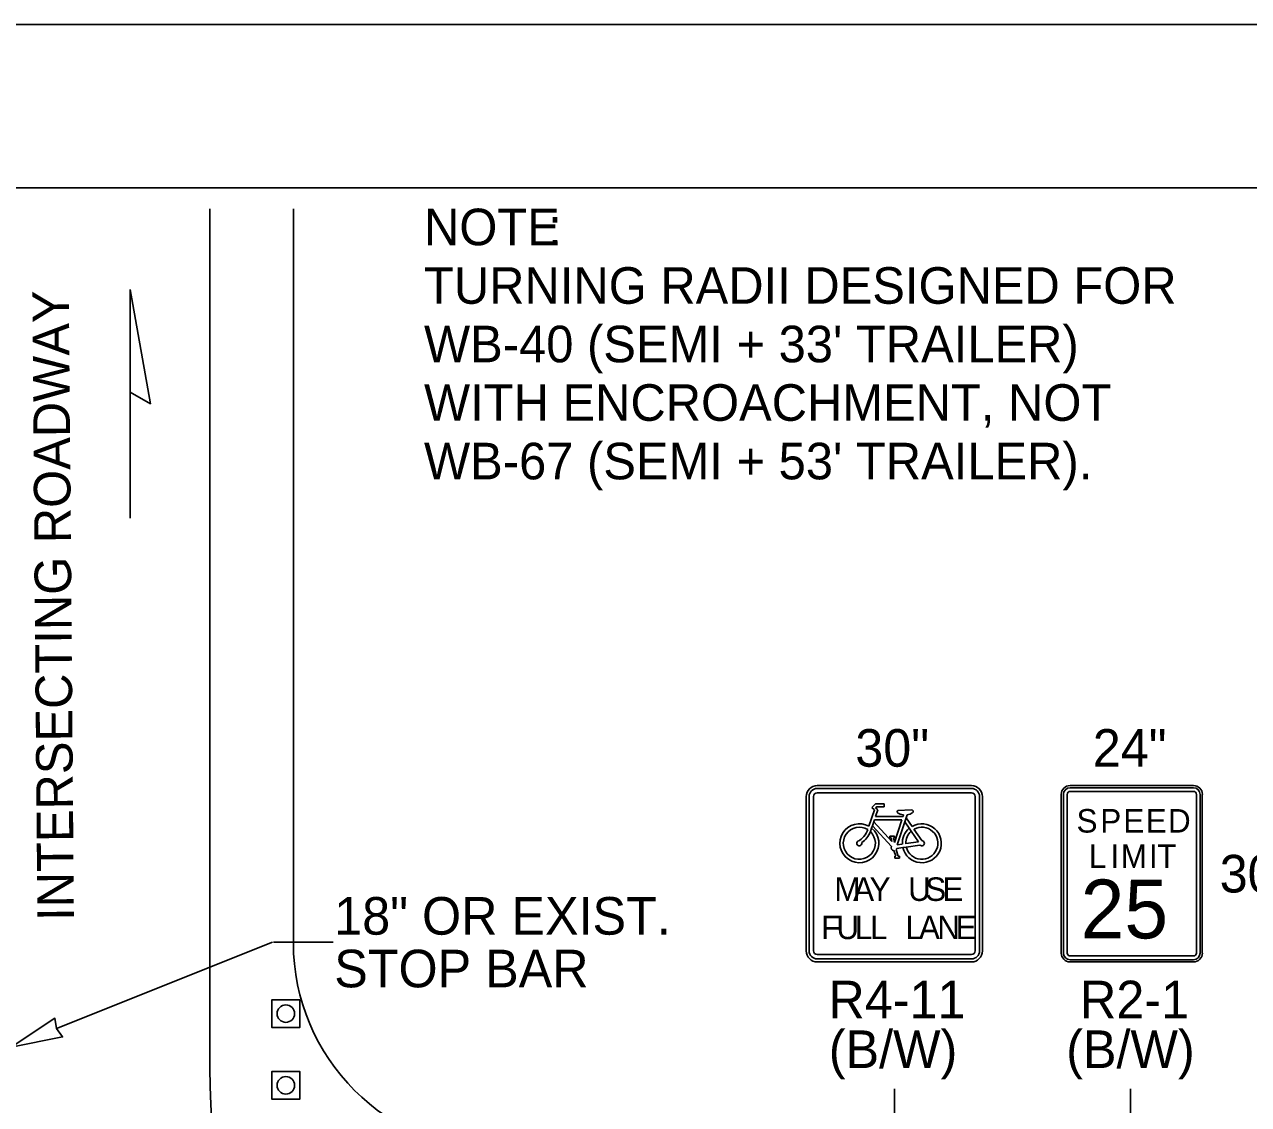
# Model space of a CAD drawing. Extents: x 99979.8 to 100075.7, y 99995 to 100010.7.
# Drawn here: x 100048.053 to 100050.396, y 100008.621 to 100010.687 of the extents above; entities that cross this region are included whole.
import ezdxf

# ---------------------------------------------------------------- set-up
doc = ezdxf.new("R2010")
doc.units = 0
for name, color, linetype in [('RD_ED_ShoulderPavedEdge', 7, 'Continuous'), ('RD_MK_LineEdgeWhite', 7, 'Continuous'), ('RD_MK_LineEdgeWhiteNew', 7, 'Continuous'), ('SH_DE_DetailBody1Text', 7, 'Continuous'), ('SH_GI_PlotLimits', 7, 'Continuous'), ('SH_GI_SheetBorder', 7, 'Continuous'), ('TR_SN_ConstructionSigns', 7, 'Continuous'), ('TR_WZ_TrafficCone', 7, 'Continuous'), ('TR_WZ_WorkZoneDetails', 7, 'Continuous'), ('TR_WZ_WorkZoneTextCurrent', 7, 'Continuous')]:
    doc.layers.add(name, color=color, linetype=linetype)

msp = doc.modelspace()

# ---------------------------------------------------------------- linework, layer by layer
at = {"layer": 'RD_ED_ShoulderPavedEdge'}
msp.add_lwpolyline([(100048.5675, 100010.335), (100048.5675, 100008.9304)], dxfattribs=at)
msp.add_arc((100048.9675, 100008.9304), 0.4, 180, 270, dxfattribs=at)
at = {"layer": 'RD_MK_LineEdgeWhite'}
for p, q in [((100048.4075, 100008.9304), (100048.4075, 100010.335)), ((100048.4075, 100008.6904), (100048.4075, 100008.9304))]:
    msp.add_line(p, q, dxfattribs=at)
at = {"layer": 'RD_MK_LineEdgeWhiteNew'}
msp.add_arc((100049.9075, 100008.6984), 1.5, 180.3046, 262.7399, dxfattribs=at)
at = {"layer": 'SH_GI_PlotLimits'}
msp.add_lwpolyline([(100039.0625, 99999.6875), (100056.0625, 99999.6875), (100056.0625, 100010.6875), (100039.0625, 100010.6875)], close=True, dxfattribs=at)
at = {"layer": 'SH_GI_SheetBorder'}
msp.add_line((100040, 100010.375), (100055.75, 100010.375), dxfattribs=at)
at = {"layer": 'TR_SN_ConstructionSigns'}
for p, q in [((100049.5702, 100009.231), (100049.8655, 100009.231)), ((100049.8655, 100009.231), (100049.5702, 100009.231)), ((100049.8655, 100009.231), (100049.5702, 100009.231)), ((100050.0542, 100009.231), (100050.2905, 100009.231)), ((100050.2905, 100009.231), (100050.0542, 100009.231)), ((100050.2905, 100009.231), (100050.0542, 100009.231)), ((100050.2905, 100009.2268), (100050.0542, 100009.2268)), ((100049.5491, 100008.9146), (100049.5491, 100009.2099)), ((100049.5491, 100009.2099), (100049.5491, 100008.9146)), ((100049.5491, 100009.2099), (100049.5491, 100008.9146)), ((100049.5547, 100009.2099), (100049.5547, 100008.9146)), ((100049.5632, 100008.9146), (100049.5632, 100009.2099)), ((100049.8655, 100009.2254), (100049.5702, 100009.2254)), ((100049.5702, 100009.217), (100049.8655, 100009.217)), ((100049.8725, 100009.2099), (100049.8725, 100008.9146)), ((100049.881, 100008.9146), (100049.881, 100009.2099)), ((100049.8866, 100009.2099), (100049.8866, 100008.9146)), ((100049.8866, 100008.9146), (100049.8866, 100009.2099)), ((100049.8866, 100008.9146), (100049.8866, 100009.2099)), ((100050.0373, 100008.9104), (100050.0373, 100009.2141)), ((100050.0373, 100009.2141), (100050.0373, 100008.9104)), ((100050.0373, 100009.2141), (100050.0373, 100008.9104)), ((100050.0416, 100009.2141), (100050.0416, 100008.9104)), ((100050.0486, 100008.9104), (100050.0486, 100009.2141)), ((100050.0542, 100009.2198), (100050.2905, 100009.2198)), ((100050.2961, 100009.2141), (100050.2961, 100008.9104)), ((100050.3031, 100008.9104), (100050.3031, 100009.2141)), ((100050.3073, 100009.2141), (100050.3073, 100008.9104)), ((100050.3073, 100008.9104), (100050.3073, 100009.2141)), ((100050.3073, 100008.9104), (100050.3073, 100009.2141)), ((100049.6796, 100009.1842), (100049.6692, 100009.1531)), ((100049.6819, 100009.1959), (100049.6749, 100009.1889)), ((100049.6749, 100009.1889), (100049.6796, 100009.1842)), ((100049.6818, 100009.1717), (100049.6859, 100009.1842)), ((100049.6983, 100009.1959), (100049.6819, 100009.1959)), ((100049.682, 100009.1882), (100049.6841, 100009.1904)), ((100049.6859, 100009.1842), (100049.682, 100009.1882)), ((100049.6841, 100009.1904), (100049.6983, 100009.1904)), ((100049.6983, 100009.1904), (100049.6983, 100009.1959)), ((100049.7503, 100009.1846), (100049.7254, 100009.183)), ((100049.6759, 100009.1542), (100049.6783, 100009.1614)), ((100049.6783, 100009.1614), (100049.6796, 100009.1652)), ((100049.713, 100009.1237), (100049.6783, 100009.1614)), ((100049.6796, 100009.1652), (100049.7322, 100009.1652)), ((100049.7344, 100009.1717), (100049.6818, 100009.1717)), ((100049.7322, 100009.1652), (100049.7178, 100009.1219)), ((100049.7232, 100009.1173), (100049.7379, 100009.1616)), ((100049.7355, 100009.1751), (100049.7344, 100009.1717)), ((100049.7406, 100009.1694), (100049.7379, 100009.1616)), ((100049.7379, 100009.1616), (100049.7464, 100009.1492)), ((100049.7406, 100009.1694), (100049.7425, 100009.1752)), ((100049.7517, 100009.1529), (100049.7406, 100009.1694)), ((100049.6744, 100009.1496), (100049.6721, 100009.1428)), ((100049.6744, 100009.1496), (100049.6759, 100009.1542)), ((100049.6759, 100009.1542), (100049.7126, 100009.1145)), ((100049.7183, 100009.1344), (100049.7095, 100009.1344)), ((100049.7183, 100009.1311), (100049.7183, 100009.1344)), ((100049.7464, 100009.1492), (100049.7501, 100009.1437)), ((100049.7501, 100009.1437), (100049.7639, 100009.1234)), ((100049.7703, 100009.1256), (100049.7554, 100009.1475)), ((100049.7116, 100009.1311), (100049.713, 100009.1237)), ((100049.7178, 100009.1219), (100049.7161, 100009.1311)), ((100049.7161, 100009.1311), (100049.7183, 100009.1311)), ((100049.7227, 100009.1106), (100049.734, 100009.1123)), ((100049.7331, 100009.1188), (100049.7232, 100009.1173)), ((100049.734, 100009.1123), (100049.7406, 100009.1132)), ((100049.7639, 100009.1234), (100049.7397, 100009.1198)), ((100049.7406, 100009.1132), (100049.7669, 100009.1171)), ((100049.7169, 100009.1064), (100049.7205, 100009.0956)), ((100049.7205, 100009.0956), (100049.7187, 100009.0956)), ((100049.7187, 100009.0956), (100049.7187, 100009.0923)), ((100049.7187, 100009.0923), (100049.7274, 100009.0923)), ((100049.7251, 100009.0956), (100049.721, 100009.1077)), ((100049.7274, 100009.0956), (100049.7251, 100009.0956)), ((100049.7274, 100009.0923), (100049.7274, 100009.0956)), ((100049.8655, 100008.9076), (100049.5702, 100008.9076)), ((100049.5702, 100008.8991), (100049.8655, 100008.8991)), ((100050.2905, 100008.9048), (100050.0542, 100008.9048)), ((100049.8655, 100008.8935), (100049.5702, 100008.8935)), ((100049.5702, 100008.8935), (100049.8655, 100008.8935)), ((100049.5702, 100008.8935), (100049.8655, 100008.8935)), ((100050.0542, 100008.8977), (100050.2905, 100008.8977)), ((100050.2905, 100008.8935), (100050.0542, 100008.8935)), ((100050.0542, 100008.8935), (100050.2905, 100008.8935)), ((100050.0542, 100008.8935), (100050.2905, 100008.8935))]:
    msp.add_line(p, q, dxfattribs=at)
msp.add_lwpolyline([(100049.7095, 100009.1344), (100049.7095, 100009.1311), (100049.7116, 100009.1311)], dxfattribs=at)
for centre, radius, start, end in [((100049.5702, 100009.2099), 0.0211, 90, 180), ((100049.5702, 100009.2099), 0.0211, 90, 180), ((100049.5702, 100009.2099), 0.0211, 90, 180), ((100049.8655, 100009.2099), 0.0211, 0, 90), ((100049.8655, 100009.2099), 0.0211, 0, 90), ((100049.8655, 100009.2099), 0.0211, 0, 90), ((100050.0542, 100009.2141), 0.0169, 90, 180), ((100050.0542, 100009.2141), 0.0169, 90, 180), ((100050.0542, 100009.2141), 0.0169, 90, 180), ((100050.0542, 100009.2141), 0.0127, 90, 180), ((100050.2905, 100009.2141), 0.0169, 0, 90), ((100050.2905, 100009.2141), 0.0169, 0, 90), ((100050.2905, 100009.2141), 0.0169, 0, 90), ((100050.2905, 100009.2141), 0.0127, 0, 90), ((100049.5702, 100009.2099), 0.0155, 90, 180), ((100049.5702, 100009.2099), 0.00703, 90, 180), ((100049.8655, 100009.2099), 0.0155, 0, 90), ((100049.8655, 100009.2099), 0.00703, 0, 90), ((100050.0542, 100009.2141), 0.00562, 90, 180), ((100050.2905, 100009.2141), 0.00562, 0, 90), ((100049.7254, 100009.1808), 0.00219, 89.3854, 243.6828), ((100049.7506, 100009.1814), 0.00329, 294.5519, 96.4128), ((100049.6508, 100009.1206), 0.0373, 60.5529, 50.868), ((100049.7704, 100009.1206), 0.0373, 192.9622, 119.9648), ((100049.6508, 100009.1206), 0.0307, 58.1532, 46.1649), ((100049.7704, 100009.1206), 0.0373, 130.0889, 182.8379), ((100049.7704, 100009.1206), 0.0307, 131.3616, 181.6359), ((100049.7704, 100009.1206), 0.0307, 193.937, 119.0598), ((100049.6508, 100009.1206), 0.00493, 105.257, 14.3233), ((100049.7174, 100009.1118), 0.00548, 151.1744, 264.8566), ((100049.7174, 100009.1118), 0.00548, 312.0053, 347.2932), ((100049.7704, 100009.1206), 0.00493, 225.1095, 90.4672), ((100049.5702, 100008.9146), 0.0211, 180, 270), ((100049.5702, 100008.9146), 0.0211, 180, 270), ((100049.5702, 100008.9146), 0.0211, 180, 270), ((100049.5702, 100008.9146), 0.0155, 180, 270), ((100049.5702, 100008.9146), 0.00703, 180, 270), ((100049.8655, 100008.9146), 0.0211, 270, 0), ((100049.8655, 100008.9146), 0.0211, 270, 0), ((100049.8655, 100008.9146), 0.0155, 270, 0), ((100049.8655, 100008.9146), 0.00703, 270, 0), ((100049.8655, 100008.9146), 0.0211, 270, 0), ((100050.0542, 100008.9104), 0.0169, 180, 270), ((100050.0542, 100008.9104), 0.0169, 180, 270), ((100050.0542, 100008.9104), 0.0169, 180, 270), ((100050.0542, 100008.9104), 0.0127, 180, 270), ((100050.0542, 100008.9104), 0.00562, 180, 270), ((100050.2905, 100008.9104), 0.0169, 270, 0), ((100050.2905, 100008.9104), 0.0169, 270, 0), ((100050.2905, 100008.9104), 0.0127, 270, 0), ((100050.2905, 100008.9104), 0.00562, 270, 0), ((100050.2905, 100008.9104), 0.0169, 270, 0)]:
    msp.add_arc(centre, radius, start, end, dxfattribs=at)
for centre, major_axis, ratio, start_param, end_param in [((100049.7385, 100009.1859), (-0.0186, 0), 0.588235, 0.686048, 1.410588), ((100049.7385, 100009.1859), (-0.0186, 0), 0.588235, 1.786993, 2.401245), ((100049.6557, 100009.1414), (-0.0105, -0.0158), 0.413554, 0.494612, 2.170849), ((100049.6557, 100009.1414), (-0.014, -0.021), 0.55814, 0.868091, 1.989998)]:
    msp.add_ellipse(centre, major_axis=major_axis, ratio=ratio, start_param=start_param, end_param=end_param, dxfattribs=at)
at = {"layer": 'TR_WZ_TrafficCone'}
for points in [[(100048.5798, 100008.8212), (100048.5264, 100008.8212), (100048.5264, 100008.7678), (100048.5798, 100008.7678), (100048.5798, 100008.8212)], [(100048.5798, 100008.7678), (100048.5264, 100008.7678), (100048.5264, 100008.8212), (100048.5798, 100008.8212), (100048.5798, 100008.7678)], [(100048.5798, 100008.684), (100048.5264, 100008.684), (100048.5264, 100008.6307), (100048.5798, 100008.6307), (100048.5798, 100008.684)], [(100048.5798, 100008.6307), (100048.5264, 100008.6307), (100048.5264, 100008.684), (100048.5798, 100008.684), (100048.5798, 100008.6307)]]:
    msp.add_lwpolyline(points, dxfattribs=at)
for centre in [(100048.5531, 100008.7945), (100048.5531, 100008.6573)]:
    msp.add_circle(centre, 0.0167, dxfattribs=at)
at = {"layer": 'TR_WZ_WorkZoneDetails'}
for p, q in [((100048.2552, 100009.9839), (100048.2552, 100009.7428)), ((100048.5274, 100008.9312), (100048.1143, 100008.766)), ((100048.6437, 100008.9312), (100048.5295, 100008.9312)), ((100049.7179, 100008.6504), (100049.7179, 100007.4184)), ((100050.17, 100008.6504), (100050.17, 100007.4184))]:
    msp.add_line(p, q, dxfattribs=at)
for points in [[(100048.2552, 100010.1804), (100048.2938, 100009.9616), (100048.2552, 100009.9839)], [(100048.0275, 100008.7304), (100048.1258, 100008.7499), (100048.1143, 100008.766), (100048.1112, 100008.7856)]]:
    msp.add_lwpolyline(points, close=True, dxfattribs=at)

# ---------------------------------------------------------------- texts
at = {"layer": 'SH_DE_DetailBody1Text'}
msp.add_text('INTERSECTING ROADWAY', height=0.07, rotation=90.4626, dxfattribs=at).set_placement((100048.1475, 100008.9722))
at = {"layer": 'TR_SN_ConstructionSigns'}
for s, p in [('30"', (100049.6431, 100009.267)), ('24"', (100050.0976, 100009.267)), ('30"', (100050.3406, 100009.0263)), ('R4-11', (100049.5916, 100008.7855)), ('R2-1', (100050.0732, 100008.7855)), ('(B/W)', (100049.5924, 100008.6904)), ('(B/W)', (100050.0468, 100008.6904))]:
    msp.add_text(s, height=0.072, rotation=360, dxfattribs=at).set_placement(p)
for s, height, p in [('S', 0.045, (100050.0666, 100009.141)), ('P', 0.045, (100050.112, 100009.141)), ('E', 0.045, (100050.1561, 100009.141)), ('E', 0.045, (100050.1989, 100009.141)), ('D', 0.045, (100050.2416, 100009.141)), ('L', 0.045, (100050.09, 100009.0735)), ('I', 0.045, (100050.1314, 100009.0735)), ('M', 0.045, (100050.1512, 100009.0735)), ('I', 0.045, (100050.2052, 100009.0735)), ('T', 0.045, (100050.2209, 100009.0735)), ('M', 0.045, (100049.6029, 100009.0102)), ('A', 0.045, (100049.6389, 100009.0102)), ('Y', 0.045, (100049.6704, 100009.0102)), ('U', 0.045, (100049.7442, 100009.0102)), ('S', 0.045, (100049.777, 100009.0102)), ('E', 0.045, (100049.8099, 100009.0102)), ('25', 0.1125, (100050.0745, 100008.9385)), ('F', 0.045, (100049.5777, 100008.9371)), ('U', 0.045, (100049.6069, 100008.9371)), ('L', 0.045, (100049.642, 100008.9371)), ('L', 0.045, (100049.6713, 100008.9371)), ('L', 0.045, (100049.7392, 100008.9371)), ('A', 0.045, (100049.7649, 100008.9371)), ('N', 0.045, (100049.8, 100008.9371)), ('E', 0.045, (100049.8351, 100008.9371))]:
    msp.add_text(s, height=height, dxfattribs=at).set_placement(p)
at = {"layer": 'TR_WZ_WorkZoneDetails'}
for s, p in [('NOTE', (100048.8175, 100010.265)), (':', (100049.0552, 100010.265)), ('TURNING RADII DESIGNED FOR ', (100048.8175, 100010.153)), ("WB-40 (SEMI + 33' TRAILER) ", (100048.8175, 100010.041)), ('WITH ENCROACHMENT, NOT ', (100048.8175, 100009.929)), ("WB-67 (SEMI + 53' TRAILER).", (100048.8175, 100009.817))]:
    msp.add_text(s, height=0.07, dxfattribs=at).set_placement(p)
at = {"layer": 'TR_WZ_WorkZoneTextCurrent'}
for s, p in [('18" OR EXIST.', (100048.6457, 100008.9456)), ('STOP BAR', (100048.6457, 100008.8448))]:
    msp.add_text(s, height=0.072, dxfattribs=at).set_placement(p)

doc.saveas('drawing.dxf')
